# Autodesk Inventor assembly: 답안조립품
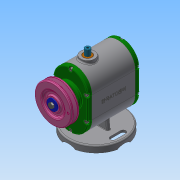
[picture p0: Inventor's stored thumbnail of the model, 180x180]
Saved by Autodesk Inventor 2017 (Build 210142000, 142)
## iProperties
Part Number: 답안조립품
Material: 일반
Document SubType Name: Assembly
Designer: user
Mass: 3121.33 g
Surface Area: 2356.35 cm^2
Volume: 792.079 cm^3
Density: 3.94068 g/cm^3
Author: user
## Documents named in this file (19)
- C:\Users\user\Desktop\611006V1007\답안조립품.iam
- C:\Users\user\Desktop\611006V1007\본체.ipt
- C:\Users\user\Desktop\611006V1007\V-벨트풀리.ipt
- C:\Users\user\Desktop\611006V1007\가변스프링.ipt
- C:\Users\user\Desktop\611006V1007\뒤커버.ipt
- C:\Users\user\Desktop\611006V1007\멈춤나사 M3.ipt
- C:\Users\user\Desktop\611006V1007\메인축.ipt
- C:\Users\user\Desktop\611006V1007\베어링 608.ipt
- C:\Users\user\Desktop\611006V1007\베어링 6003.ipt
- C:\Users\user\Desktop\611006V1007\볼트 M4.ipt
- C:\Users\user\Desktop\611006V1007\볼트 M6.ipt
- C:\Users\user\Desktop\611006V1007\부시.ipt
- C:\Users\user\Desktop\611006V1007\서브축.ipt
- C:\Users\user\Desktop\611006V1007\슬라이더.ipt
- C:\Users\user\Desktop\611006V1007\앞커버.ipt
- C:\Users\user\Desktop\611006V1007\오일실 8x22x7.ipt
- C:\Users\user\Desktop\611006V1007\오일실 17x32x8.ipt
- C:\Users\user\Desktop\611006V1007\와셔.ipt
- C:\Users\user\Desktop\611006V1007\키 5x5.ipt
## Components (2 placed, 2 different names)
1. V-벨트풀리:1
2. 가변스프링:1
